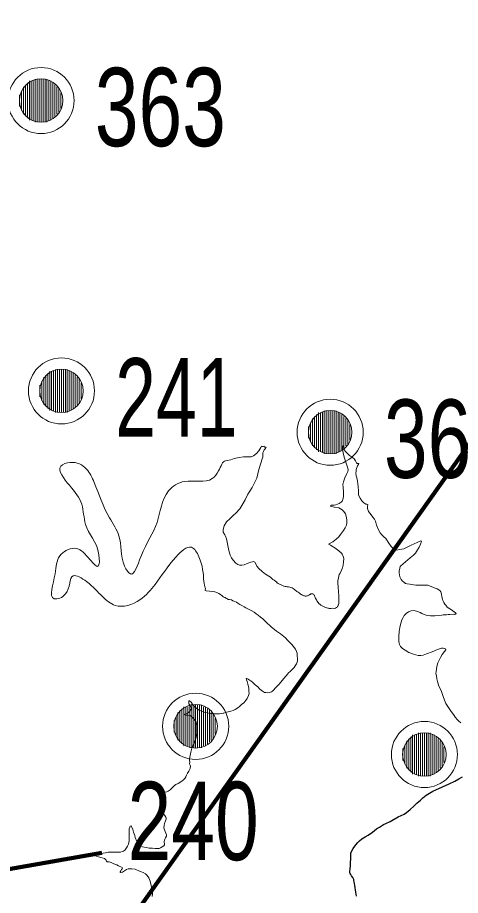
# Model space of a CAD drawing. Extents: x 553962 to 842807, y 8883888 to 9032388.
# Drawn here: x 708296 to 710557, y 8963822 to 8968303 of the extents above; entities that cross this region are included whole.
import ezdxf

# ---------------------------------------------------------------- set-up
doc = ezdxf.new("R2010")
doc.units = 0
doc.header["$LTSCALE"] = 160
for name, color, linetype, lineweight in [('21', 7, 'Continuous', 25), ('27', 7, 'Continuous', 90), ('33', 7, 'Continuous', 13), ('7', 7, 'Continuous', 90), ('8', 7, 'Continuous', 13)]:
    doc.layers.add(name, color=color, linetype=linetype, lineweight=lineweight)

msp = doc.modelspace()

# ---------------------------------------------------------------- linework, layer by layer
at = {"layer": '21'}
for points in [[(710000.6, 8963922), (709997.1, 8963929.1), (709994.4, 8963933.2), (709992.9, 8963937.1), (709992.3, 8963944.1), (709993.5, 8963956.8), (709995.3, 8963972.7), (709995.9, 8963988.3), (709997, 8964009.5), (709997, 8964025.7), (709997.6, 8964037.2), (710000.6, 8964046.7), (710009.7, 8964060.8), (710023.7, 8964079.6), (710032.8, 8964091.9), (710040.8, 8964100.5), (710053.5, 8964110.8), (710070.6, 8964121.1), (710085.3, 8964130), (710108.5, 8964144.7), (710128.6, 8964161.2), (710143.6, 8964170.3), (710163.7, 8964183.3), (710175.5, 8964189.5), (710198.5, 8964199.8), (710207.1, 8964204.8), (710239.1, 8964222.6), (710269, 8964236.8), (710280.8, 8964244.5), (710300.8, 8964260.7), (710318.8, 8964277.8), (710324.1, 8964282.8), (710334.9, 8964292.4), (710352.3, 8964308), (710365.6, 8964319.5), (710381.8, 8964332.8), (710398.6, 8964344), (710415.8, 8964353.7), (710432, 8964361.1), (710465.5, 8964376), (710498.9, 8964391), (710528.1, 8964404.3), (710549.6, 8964416.4), (710567.2, 8964426.9)], [(710025.7, 8963818.7), (710024.6, 8963828.1), (710023.1, 8963838.4), (710020.4, 8963850.5), (710018.7, 8963860.5), (710017.8, 8963872.3), (710015.7, 8963882.9), (710013.9, 8963891.5), (710012.2, 8963898), (710012.1, 8963902.3), (710011.2, 8963906.7), (710007.7, 8963913.2), (710000.6, 8963922)]]:
    msp.add_lwpolyline(points, dxfattribs=at)
at = {"layer": '27'}
msp.add_lwpolyline([(691582, 8951218.7), (697371.2, 8956056), (705081.2, 8958366.8), (713138.6, 8969695)], dxfattribs=at)
at = {"layer": '33'}
for p, q in [((708356, 8967979), (708356, 8967779)), ((708366, 8967979), (708366, 8967779)), ((708376, 8967979), (708376, 8967779)), ((708386, 8967989), (708386, 8967769)), ((708396, 8967989), (708396, 8967769)), ((708406, 8967989), (708406, 8967769)), ((708416, 8967989), (708416, 8967769)), ((708426, 8967989), (708426, 8967769)), ((708436, 8967989), (708436, 8967769)), ((708446, 8967989), (708446, 8967769)), ((708456, 8967979), (708456, 8967779)), ((708466, 8967979), (708466, 8967779)), ((708316, 8967929), (708316, 8967829)), ((708326, 8967949), (708326, 8967809)), ((708336, 8967959), (708336, 8967799)), ((708346, 8967969), (708346, 8967789)), ((708476, 8967969), (708476, 8967789)), ((708486, 8967959), (708486, 8967799)), ((708496, 8967949), (708496, 8967809)), ((708506, 8967939), (708506, 8967819)), ((708306, 8967909), (708306, 8967849)), ((708516, 8967919), (708516, 8967839)), ((708460, 8966497), (708460, 8966297)), ((708470, 8966497), (708470, 8966297)), ((708480, 8966497), (708480, 8966297)), ((708490, 8966507), (708490, 8966287)), ((708500, 8966507), (708500, 8966287)), ((708510, 8966507), (708510, 8966287)), ((708520, 8966507), (708520, 8966287)), ((708530, 8966507), (708530, 8966287)), ((708540, 8966507), (708540, 8966287)), ((708550, 8966507), (708550, 8966287)), ((708560, 8966497), (708560, 8966297)), ((708570, 8966497), (708570, 8966297)), ((708430, 8966467), (708430, 8966327)), ((708440, 8966477), (708440, 8966317)), ((708450, 8966487), (708450, 8966307)), ((708580, 8966487), (708580, 8966307)), ((708590, 8966477), (708590, 8966317)), ((708600, 8966467), (708600, 8966327)), ((708610, 8966457), (708610, 8966337)), ((708410, 8966427), (708410, 8966367)), ((708420, 8966447), (708420, 8966347)), ((708620, 8966437), (708620, 8966357)), ((709822, 8966276), (709822, 8966096)), ((709832, 8966286), (709832, 8966086)), ((709842, 8966286), (709842, 8966086)), ((709852, 8966286), (709852, 8966086)), ((709862, 8966296), (709862, 8966076)), ((709872, 8966296), (709872, 8966076)), ((709882, 8966296), (709882, 8966076)), ((709892, 8966296), (709892, 8966076)), ((709902, 8966296), (709902, 8966076)), ((709912, 8966296), (709912, 8966076)), ((709922, 8966296), (709922, 8966076)), ((709932, 8966286), (709932, 8966086)), ((709942, 8966286), (709942, 8966086)), ((709952, 8966276), (709952, 8966096)), ((709792, 8966236), (709792, 8966136)), ((709802, 8966256), (709802, 8966116)), ((709812, 8966266), (709812, 8966106)), ((709962, 8966266), (709962, 8966106)), ((709972, 8966256), (709972, 8966116)), ((709982, 8966246), (709982, 8966126)), ((709992, 8966226), (709992, 8966146)), ((709782, 8966216), (709782, 8966156)), ((709175, 8964795), (709175, 8964575)), ((709185, 8964795), (709185, 8964575)), ((709195, 8964795), (709195, 8964575)), ((709205, 8964795), (709205, 8964575)), ((709215, 8964795), (709215, 8964575)), ((709225, 8964795), (709225, 8964575)), ((709235, 8964795), (709235, 8964575)), ((709115, 8964755), (709115, 8964615)), ((709125, 8964765), (709125, 8964605)), ((709135, 8964775), (709135, 8964595)), ((709145, 8964785), (709145, 8964585)), ((709155, 8964785), (709155, 8964585)), ((709165, 8964785), (709165, 8964585)), ((709245, 8964785), (709245, 8964585)), ((709255, 8964785), (709255, 8964585)), ((709265, 8964775), (709265, 8964595)), ((709275, 8964765), (709275, 8964605)), ((709285, 8964755), (709285, 8964615)), ((709295, 8964745), (709295, 8964625)), ((709095, 8964715), (709095, 8964655)), ((709105, 8964735), (709105, 8964635)), ((709305, 8964725), (709305, 8964645)), ((710283, 8964611), (710283, 8964471)), ((710293, 8964621), (710293, 8964461)), ((710303, 8964631), (710303, 8964451)), ((710313, 8964641), (710313, 8964441)), ((710323, 8964641), (710323, 8964441)), ((710333, 8964641), (710333, 8964441)), ((710343, 8964651), (710343, 8964431)), ((710353, 8964651), (710353, 8964431)), ((710363, 8964651), (710363, 8964431)), ((710373, 8964651), (710373, 8964431)), ((710383, 8964651), (710383, 8964431)), ((710393, 8964651), (710393, 8964431)), ((710403, 8964651), (710403, 8964431)), ((710413, 8964641), (710413, 8964441)), ((710423, 8964641), (710423, 8964441)), ((710433, 8964631), (710433, 8964451)), ((710443, 8964621), (710443, 8964461)), ((710453, 8964611), (710453, 8964471)), ((710263, 8964571), (710263, 8964511)), ((710273, 8964591), (710273, 8964491)), ((710463, 8964601), (710463, 8964481)), ((710473, 8964581), (710473, 8964501))]:
    msp.add_line(p, q, dxfattribs=at)
for centre, radius in [((708416, 8967879), 168.7), ((708416, 8967879), 111), ((708520, 8966397), 168.7), ((708520, 8966397), 111), ((709892, 8966186), 168.7), ((709892, 8966186), 111), ((709205, 8964685), 168.7), ((709205, 8964685), 111), ((710373, 8964541), 168.7), ((710373, 8964541), 111)]:
    msp.add_circle(centre, radius, dxfattribs=at)
at = {"layer": '7'}
msp.add_lwpolyline([(706465.3, 8963944.5), (707513.2, 8963827.1), (708725.4, 8964038.4)], dxfattribs=at)
at = {"layer": '8'}
for points in [[(709356.7, 8966039.9), (709366.8, 8966040.9), (709384, 8966045.7), (709402.1, 8966052.6), (709427.2, 8966057.7), (709450.1, 8966060.8), (709477.9, 8966060.8), (709489.2, 8966061.1), (709500.2, 8966065.2), (709515.6, 8966078.3), (709528, 8966090.6), (709538.2, 8966108.8), (709541, 8966114.6), (709546.1, 8966112.5), (709551.6, 8966112.9), (709554.7, 8966114.2), (709556.8, 8966109.8), (709561.9, 8966109.1), (709564.7, 8966109.8), (709561.9, 8966103.3), (709554.7, 8966095.7), (709551.3, 8966088.2), (709548.2, 8966081.3), (709547.5, 8966069.7), (709547.5, 8966059.4), (709545.5, 8966049.8), (709538.2, 8966028.9), (709527.3, 8965996), (709523.2, 8965974.1), (709517.1, 8965951.5), (709503.1, 8965925.1), (709493.5, 8965903.9), (709481.1, 8965885.4), (709471.2, 8965869.6), (709457.5, 8965840.5), (709441.7, 8965811.7), (709430.2, 8965795), (709410, 8965772.7), (709398.7, 8965763.5), (709380.9, 8965744.9), (709363.4, 8965728.5), (709351.1, 8965708.8), (709346, 8965690.2), (709345.3, 8965676.1), (709354.7, 8965662.1)], [(709931, 8965418.8), (709931.7, 8965428), (709934.6, 8965443.3), (709937.9, 8965459.3), (709943, 8965467.5), (709949.7, 8965482.4), (709954.1, 8965493.7), (709957.4, 8965507.7), (709960.1, 8965525.2), (709961.8, 8965539.5), (709960, 8965548.9), (709953.6, 8965562.9), (709949.5, 8965568.9), (709936.3, 8965581.5), (709915.5, 8965596.7), (709893.5, 8965609), (709883.3, 8965614.3), (709905.2, 8965626.9), (709923.1, 8965640.1), (709935.4, 8965652.1), (709945.4, 8965664.1), (709960.7, 8965684.1), (709969.2, 8965698.8), (709974.5, 8965711.1), (709976.5, 8965723.6), (709977.1, 8965735.3), (709975.6, 8965750.6), (709969.5, 8965769.9), (709961.9, 8965781), (709953.1, 8965790.7), (709936.7, 8965799.8), (709913.8, 8965803.8), (709901.2, 8965806.1), (709895.1, 8965807.8), (709893.3, 8965811), (709898.9, 8965813.4), (709912.7, 8965813.7), (709921.2, 8965815.4), (709937.8, 8965822.2), (709948.1, 8965829.5), (709952.8, 8965834.8), (709956.6, 8965842.7), (709959.5, 8965858.2), (709960.4, 8965880.4), (709958.9, 8965905.9), (709957.2, 8965919.7), (709960.1, 8965932.8), (709967.5, 8965952.7), (709977.7, 8965975.8), (709982.4, 8965986.3), (709984.2, 8965994.8), (709981.8, 8966003.3), (709971.3, 8966033.5), (709962.5, 8966059.2), (709957.8, 8966081.5), (709954.6, 8966099.9), (709954.6, 8966111.3), (709956, 8966116.3), (709959.6, 8966111.9), (709962.2, 8966103.1), (709965.4, 8966095.2), (709970.4, 8966087.3), (709980.3, 8966078), (709991.2, 8966068), (710006.4, 8966057.5), (710014.6, 8966049.9), (710021.9, 8966040.2), (710026.3, 8966030.2), (710029.8, 8966025.9), (710036, 8966025.9), (710037.5, 8966025.3), (710035.7, 8966021.2), (710031, 8966014.7), (710024.9, 8965996), (710024.3, 8965986.9), (710022.5, 8965977.6), (710025.2, 8965963.5), (710028.7, 8965953.8), (710031.3, 8965935.7), (710034.2, 8965908.8), (710035.7, 8965885.8), (710036.9, 8965870.5), (710038.4, 8965861.2), (710044.2, 8965849.5), (710054.2, 8965835.1), (710063.8, 8965826), (710073.5, 8965819.6), (710079.1, 8965818.1), (710083.5, 8965817.8), (710082.6, 8965807.3), (710083.2, 8965795.9), (710088.1, 8965782.1), (710094.9, 8965773.1), (710101.6, 8965764.6), (710110.5, 8965753), (710118.1, 8965742.4), (710122.8, 8965731.9), (710128.1, 8965712.3), (710136.8, 8965691.5), (710147.1, 8965671.9), (710155.6, 8965662.2)], [(709354.7, 8965662.1), (709358.1, 8965655.8), (709362.9, 8965642.3), (709369.2, 8965608.6), (709374.1, 8965582.5), (709381.7, 8965558.6), (709387.3, 8965544.7), (709396.6, 8965532.5), (709409.5, 8965517.9), (709420.6, 8965510.6), (709429.7, 8965506.8), (709440.4, 8965506.8), (709452.2, 8965508.9), (709468.9, 8965516.2), (709486.3, 8965522.8), (709495.3, 8965524.9), (709500.9, 8965525.9), (709506.8, 8965522.8), (709513.4, 8965510.3), (709517.9, 8965501.6), (709528, 8965490.8), (709544, 8965475.9), (709562.4, 8965461.6), (709586.4, 8965445.7), (709599.2, 8965434.5), (709605.8, 8965430.7), (709613.1, 8965425.2), (709619, 8965420.5)], [(710155.6, 8965662.2), (710165.6, 8965652.6), (710176.4, 8965643.2), (710192.2, 8965619), (710204, 8965602.9), (710214.2, 8965593), (710220.9, 8965587.1), (710228.8, 8965584.8), (710248.2, 8965586.8), (710268.4, 8965591.5), (710305.9, 8965609.3), (710335.4, 8965623.1), (710354.2, 8965631.6), (710356.2, 8965631.6), (710358.3, 8965628.7), (710353, 8965615.2), (710346, 8965599.1), (710337.2, 8965585.3), (710327.5, 8965569.5), (710317, 8965559.3), (710299.7, 8965544.7), (710276.6, 8965525.3), (710264.3, 8965515.1), (710253.2, 8965504.8), (710249.6, 8965500.2), (710247.3, 8965492.1), (710244.7, 8965477.2), (710243.5, 8965468.4), (710247.9, 8965448.5), (710254.9, 8965433.5), (710260.8, 8965426.5), (710265.5, 8965421.8), (710271.9, 8965417)], [(709352.9, 8965343.2), (709344.8, 8965346.1), (709340.6, 8965350.4), (709331.9, 8965357.5), (709323, 8965362.9), (709312.5, 8965367.7), (709303.6, 8965370.7), (709290.2, 8965373.9), (709275.8, 8965375.1), (709258.8, 8965376.3), (709254.1, 8965377.5), (709253.5, 8965381.4), (709254.7, 8965386.4), (709254.4, 8965392.1), (709252.6, 8965398.3), (709250.8, 8965405.2), (709248.1, 8965415), (709246.9, 8965423.6)], [(709617.3, 8965420.5), (709618.5, 8965419.4), (709620, 8965418.2), (709621.2, 8965416.9), (709625.9, 8965413.9), (709634, 8965409.9), (709644.9, 8965404.6), (709651.9, 8965401.5), (709655.8, 8965400), (709657.3, 8965399.8), (709661.8, 8965398.8), (709664.8, 8965398.3), (709667.8, 8965398.3), (709673.1, 8965397.5), (709679.1, 8965396.5), (709685.6, 8965395.2), (709691.3, 8965393.5), (709697.1, 8965391.3), (709702.2, 8965388.7), (709704.4, 8965387.2), (709709.3, 8965383.9), (709714, 8965380.1), (709718.8, 8965376), (709722.5, 8965373.4), (709727.9, 8965369.9), (709733, 8965365.9), (709737.4, 8965362.8), (709741.1, 8965360.3), (709745.2, 8965357.6), (709750.1, 8965354.6), (709754.5, 8965352.3), (709758, 8965351), (709761, 8965350.5), (709764, 8965350), (709767.4, 8965349.8), (709769.9, 8965350), (709772.9, 8965350.2), (709775.7, 8965351.2), (709779.1, 8965352.3), (709783.7, 8965354.9), (709787.3, 8965357.5), (709789.9, 8965358.6), (709794, 8965360.6), (709796.7, 8965361.7), (709798.8, 8965361.9), (709800.1, 8965362), (709801.5, 8965361.8), (709802.9, 8965361.1), (709803.9, 8965360.4), (709806.4, 8965358.7), (709809.1, 8965356.3), (709811.1, 8965353.8), (709812.2, 8965351.1), (709814, 8965347), (709814.8, 8965343.3), (709815.9, 8965340.2), (709816.9, 8965338.1), (709818.8, 8965336), (709821.9, 8965330.5), (709824.5, 8965325.5), (709830.5, 8965317.5), (709834.6, 8965312.5), (709840.4, 8965307.1), (709845, 8965303.7), (709851, 8965300), (709860.5, 8965294.9), (709868.1, 8965291.8), (709875.3, 8965289.3), (709879.3, 8965287.9), (709882.7, 8965287.6), (709887.3, 8965286.8), (709895.1, 8965286.8), (709903.6, 8965287.6), (709912.6, 8965287), (709917.8, 8965287.4), (709919.6, 8965288.1), (709924, 8965290.8), (709928.1, 8965293.8), (709928.7, 8965296.3), (709931.6, 8965298.6), (709933.5, 8965303.3), (709934.4, 8965305.5), (709935.7, 8965311), (709936.5, 8965316.4), (709936.1, 8965325.1), (709935.7, 8965336.2), (709935.7, 8965350.1), (709935.3, 8965357.3), (709934.8, 8965364.8), (709934.2, 8965378.8), (709933.2, 8965388.9), (709932, 8965399.8), (709930.7, 8965411.6), (709931.2, 8965418.8)], [(710272.5, 8965417), (710277, 8965414.3), (710284.2, 8965412.2), (710297.8, 8965409.8), (710305.6, 8965409.3), (710317.1, 8965406.3), (710329.9, 8965405.3), (710349.3, 8965405.5), (710369.9, 8965405.3), (710377.6, 8965405.8), (710383.3, 8965405.5), (710390.5, 8965404.7), (710402, 8965401), (710415.9, 8965395.4), (710427.9, 8965390.9), (710438.8, 8965386.1), (710452.2, 8965377.6), (710457.5, 8965372), (710460.7, 8965358.9), (710462.4, 8965345.4), (710464.8, 8965334.5), (710466.6, 8965327.8), (710472, 8965317.4), (710476.8, 8965308.6), (710481.9, 8965302.6), (710489.9, 8965293.5), (710503.3, 8965284.2), (710515.6, 8965276.2), (710526, 8965267.1), (710530.3, 8965265.1), (710533.8, 8965262.5), (710534.9, 8965260.4), (710533.6, 8965258.6), (710529.8, 8965256.6), (710527.5, 8965255.2), (710521.1, 8965256.7), (710502.3, 8965256.5), (710493.5, 8965255.7), (710485.4, 8965254.8), (710469.1, 8965253.2), (710462.8, 8965252.7), (710445.7, 8965250.5), (710426.6, 8965249.6), (710411.4, 8965249.4)], [(709533.5, 8964874.4), (709547.1, 8964863.9), (709555.9, 8964857.3), (709559.8, 8964857), (709564.2, 8964857), (709573.6, 8964856.4), (709581.3, 8964857), (709587.7, 8964858.4), (709592.4, 8964861.4), (709597.7, 8964865), (709605.1, 8964871.9), (709611.5, 8964880.2), (709619.9, 8964888.7), (709629.3, 8964898.1), (709639.3, 8964910.2), (709653.9, 8964926.5), (709667.7, 8964943.1), (709674.1, 8964951.7), (709679.9, 8964958.6), (709688.2, 8964965.5), (709697.3, 8964974.8), (709707.7, 8964984.5), (709713.7, 8964993.9), (709720.4, 8965003.5), (709723.7, 8965011.6), (709725.4, 8965020.1), (709725.1, 8965032.3), (709724.2, 8965043), (709724, 8965052.7), (709723.4, 8965059), (709719.8, 8965067.2), (709714.2, 8965079.1), (709703.2, 8965093.2), (709696.3, 8965101.8), (709686.3, 8965112.3), (709674.7, 8965125.2), (709663.9, 8965136.3), (709655.8, 8965143.1), (709637.5, 8965156.4), (709617.6, 8965170.8), (709590, 8965192.3), (709564.8, 8965216.3), (709547.3, 8965232.8), (709535.7, 8965242.2), (709523.8, 8965252.4), (709513.5, 8965259.1), (709503.3, 8965267.1), (709489.2, 8965275.9), (709475.1, 8965283.1), (709460.6, 8965290.2), (709452, 8965294.6), (709441, 8965300.9), (709429.9, 8965306.7), (709421, 8965312.8), (709413, 8965317.8), (709404.7, 8965321.4), (709395.6, 8965326.1), (709387.3, 8965330.2), (709378.5, 8965332.4), (709371.3, 8965333), (709369.1, 8965334.1), (709364.4, 8965337.4), (709359.1, 8965339.9), (709356.6, 8965342.1), (709352.9, 8965343.2)], [(710411.4, 8965249.4), (710403.5, 8965248.8), (710391.7, 8965250.5), (710381.6, 8965252.9), (710371.2, 8965256.4), (710359.1, 8965261.2), (710351.1, 8965265.4), (710337.6, 8965271.6), (710320.9, 8965276.5), (710305, 8965275.1), (710292.5, 8965269.2), (710280, 8965260.6), (710270, 8965249.8), (710263.9, 8965241), (710257.3, 8965227.9), (710250.4, 8965205.3)], [(710250.4, 8965205.3), (710247.3, 8965188.7), (710243.8, 8965169), (710243.1, 8965144.1), (710242, 8965126.5), (710242.4, 8965118.5), (710243.4, 8965109.8), (710245.2, 8965102.9), (710251.4, 8965092.9), (710261.5, 8965082.8), (710275.3, 8965073.1), (710293, 8965061.7), (710317.3, 8965052.7), (710328.7, 8965049.2), (710340.8, 8965047.1), (710355, 8965046.4), (710367.5, 8965048.5), (710384.4, 8965055.4), (710412.9, 8965065.4), (710439.9, 8965077.2), (710450.7, 8965080), (710460.4, 8965083.1), (710469, 8965084.2), (710476, 8965082.6), (710480.1, 8965080.4), (710482.6, 8965075.2), (710476.2, 8965066.3), (710464.1, 8965051.1), (710455.8, 8965036.2), (710449.7, 8965026.7), (710442, 8965008.2), (710435.6, 8964989.9), (710432.8, 8964965.4), (710431.7, 8964954.4), (710434.2, 8964942.2), (710435.8, 8964926.8), (710439.4, 8964913.8), (710443, 8964901.9), (710446.6, 8964890.6), (710453.2, 8964878.4), (710460.3, 8964862.5), (710469.1, 8964837.1), (710476, 8964818), (710482.7, 8964800.6), (710492.4, 8964786.5), (710506.5, 8964765.6), (710525.5, 8964739.7), (710530.8, 8964731.7), (710542.7, 8964718.1), (710547.8, 8964712.7), (710558.3, 8964703)], [(709349.7, 8964752.8), (709356.8, 8964754.8), (709363.2, 8964756.5), (709371.8, 8964759), (709384.2, 8964761.7), (709396.7, 8964766.1), (709407.2, 8964771.1), (709419.9, 8964779.4), (709428.9, 8964785.9), (709439.4, 8964795.6), (709450.4, 8964804.4), (709459.8, 8964814.9), (709468.4, 8964827.4), (709474.5, 8964842.3), (709477.5, 8964853), (709477.2, 8964862.9), (709476.9, 8964881.7), (709471.4, 8964900.8), (709468.4, 8964913.5), (709465.3, 8964922.3), (709462.8, 8964928.7), (709467, 8964928.9), (709472.8, 8964926.4), (709480, 8964921.2), (709486.1, 8964916.8), (709495.2, 8964909.6), (709500.1, 8964904.8), (709509.7, 8964896.2), (709521.9, 8964886.3), (709533.5, 8964874.4)], [(709143, 8964411.5), (709149.2, 8964418), (709154.8, 8964427.6), (709157.9, 8964435.7), (709163.5, 8964446.6), (709169.5, 8964455.8), (709173.2, 8964463.5), (709176.3, 8964469.7), (709179.1, 8964482.1), (709176.9, 8964487.4), (709174.4, 8964493.6), (709174.7, 8964502), (709173.5, 8964509.8), (709174.1, 8964518.8), (709175, 8964527.8), (709179.1, 8964543.8), (709181, 8964553.1), (709183.7, 8964566.8), (709186.2, 8964573.9), (709193.1, 8964589.5), (709197.1, 8964596.6), (709203.3, 8964613), (709207.7, 8964627.5), (709209.6, 8964638.4), (709211.2, 8964654.2), (709211.5, 8964668.2), (709210.8, 8964689.6), (709207, 8964705.6), (709203, 8964714), (709198, 8964721.4), (709191.5, 8964728.6), (709184.3, 8964734.5), (709176.3, 8964739.4), (709167.6, 8964741), (709153.6, 8964741.3), (709149.2, 8964742.8), (709147.1, 8964745), (709149.5, 8964746.9), (709154.2, 8964749.4), (709165.4, 8964754), (709173.3, 8964759.6), (709178, 8964766.8), (709181.7, 8964773.3), (709183.3, 8964778.2), (709183, 8964781.7), (709174.6, 8964794.1), (709170.9, 8964799.7), (709170.2, 8964808), (709170.9, 8964814.2), (709173.7, 8964815.2), (709181.4, 8964808.3), (709191.4, 8964794.4), (709200.4, 8964784.1), (709212.2, 8964774.5), (709223.7, 8964766.8), (709235.2, 8964761.8), (709248.8, 8964756.8), (709264.4, 8964753.4), (709279.6, 8964750.3), (709292.4, 8964749.4), (709314.4, 8964748.4), (709326.5, 8964749.1), (709337.4, 8964750.3), (709345.2, 8964752.2), (709349.7, 8964752.8)], [(709056, 8964131.7), (709053.5, 8964138.9), (709045.7, 8964156.2), (709042.6, 8964167.6), (709043.8, 8964178.5), (709046.6, 8964189.1), (709051.3, 8964201.8), (709054.4, 8964210.8), (709054.4, 8964217), (709053.1, 8964221.6), (709048.2, 8964230), (709039.4, 8964238.9), (709030.4, 8964249.2), (709024.8, 8964259.1), (709022, 8964269.3), (709022.3, 8964279.3), (709024.8, 8964292.3), (709027.9, 8964304.4), (709027.9, 8964310.3), (709024.5, 8964320.4), (709019.2, 8964329.7), (709015.8, 8964341.5), (709015.2, 8964347.4), (709020.5, 8964349), (709028.3, 8964350.2), (709036, 8964349.6), (709047.2, 8964349), (709058.1, 8964350.2), (709065.2, 8964353.6), (709075.8, 8964361.1), (709086.8, 8964372.1), (709093.9, 8964380.2), (709096.7, 8964383.2), (709104.5, 8964387.6), (709116, 8964393.2), (709135.2, 8964405.6), (709143, 8964411.5)], [(708983.4, 8963816), (708985, 8963828.1), (708985, 8963840.2), (708982.2, 8963855), (708978.4, 8963872.7), (708972.8, 8963895), (708965.7, 8963911.2), (708958.2, 8963923.6), (708949.7, 8963931.5), (708937, 8963938.9), (708918.3, 8963946), (708895.6, 8963955.3), (708879.2, 8963958.2), (708868, 8963958.2), (708860.5, 8963957.5), (708852.1, 8963954.1), (708841.6, 8963947.6), (708831, 8963940.8), (708821.7, 8963939.2), (708820.4, 8963940.5), (708820.4, 8963942.9), (708822.6, 8963947.9), (708825.7, 8963953.5), (708829.8, 8963957.5), (708831.3, 8963960.9), (708830.7, 8963964.7), (708827.3, 8963966.8), (708811.1, 8963973), (708802.4, 8963977.7), (708787, 8963983.5), (708773, 8963989.7), (708763.1, 8963993.1), (708753.2, 8963994), (708749.4, 8963996.2), (708748.2, 8964001.5), (708745.4, 8964005.8), (708740.4, 8964009.5), (708727.7, 8964014.2), (708709, 8964018.2), (708697.2, 8964022.9), (708691, 8964025.7), (708687.6, 8964033.1), (708689.5, 8964035), (708693.8, 8964035.6), (708698.8, 8964035), (708707.8, 8964033.1), (708719.9, 8964033.7), (708732.3, 8964037.5), (708744.1, 8964040), (708758.8, 8964042.1), (708773.5, 8964042.5), (708791.5, 8964043.1), (708807.4, 8964042.5), (708820.7, 8964043.4), (708830.1, 8964045.3), (708836.6, 8964048.1), (708845.3, 8964054), (708852.4, 8964063.9), (708857.7, 8964072.6), (708861.8, 8964083.2), (708865.2, 8964100.2), (708865.2, 8964113.8), (708865.8, 8964130.6), (708864.9, 8964141.8), (708865.5, 8964152.9), (708865.8, 8964162.2), (708868.3, 8964169.4), (708871.1, 8964175.3), (708875.2, 8964177.8), (708884.2, 8964157.6), (708888.5, 8964143.9), (708894.1, 8964126.9), (708896.8, 8964117.3), (708904.6, 8964096.5), (708909.8, 8964085.3), (708914.8, 8964077.9), (708922, 8964072.6), (708934.4, 8964069.5), (708953, 8964066.1), (708968.6, 8964063.3), (708985.3, 8964062.4), (708998.4, 8964061.1), (709011.8, 8964061.1), (709018.3, 8964061.8), (709025.4, 8964063.9), (709034.4, 8964069.8), (709041.9, 8964075.7), (709046, 8964080.8), (709046, 8964081)], [(709046, 8964081), (709045.1, 8964097.3), (709045.7, 8964103.5), (709047.6, 8964109.1), (709051.3, 8964115.3), (709056, 8964124), (709056, 8964131.7)]]:
    msp.add_lwpolyline(points, dxfattribs=at)
msp.add_spline([(709246.9, 8965423.6), (709222.1, 8965550.3), (709183.2, 8965599), (709105.3, 8965550.3), (708998.3, 8965409.2), (708920.5, 8965331.3), (708793.9, 8965302.1), (708730.7, 8965345.9), (708648, 8965423.8), (708579.9, 8965453), (708540.9, 8965360.5), (708482.6, 8965336.1), (708487.4, 8965462.7), (708511.7, 8965555.2), (708584.7, 8965594.1), (708657.7, 8965545.5), (708706.4, 8965501.6), (708711.2, 8965560.1), (708643.1, 8965715.8), (708623.7, 8965818.1), (708560.4, 8965915.4), (708516.6, 8966012.8), (708565.3, 8966032.3), (708648, 8965998.2), (708686.9, 8965930), (708764.8, 8965749.9), (708813.4, 8965657.4), (708842.6, 8965501.6), (708871.8, 8965462.7), (708925.3, 8965550.3), (709008, 8965725.6), (709066.4, 8965886.2), (709149.1, 8965934.9), (709290.2, 8965949.5), (709322.3, 8965988.3), (709339.1, 8966023.2), (709347.7, 8966035), (709356.7, 8966039.9)], degree=3, dxfattribs=at)

# ---------------------------------------------------------------- texts
at = {"layer": '33'}
for s, width, p in [('363', 0.75, (708690.2, 8967646.1)), ('241', 0.7, (708794.2, 8966164.1)), ('364', 0.75, (710166.2, 8965953.1)), ('240', 0.75, (708857.7, 8964001.8))]:
    msp.add_text(s, height=400, dxfattribs=dict(at, width=width)).set_placement(p)

doc.saveas('drawing.dxf')
